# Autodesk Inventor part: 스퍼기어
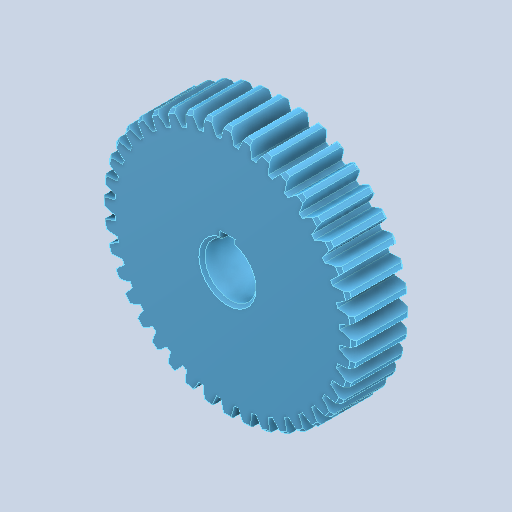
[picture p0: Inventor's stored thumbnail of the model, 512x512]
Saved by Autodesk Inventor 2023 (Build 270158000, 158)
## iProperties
Created: 2025-03
Part Number: 스퍼기어
Material: 알루미늄 6061
Document SubType Name: Modeling
Designer: ADMIN_PC
Density: 2.71 g/cm^3
Appearance: 기본값
Author: jhkim
Sending System: Autodesk Inventor 2025
Preprocessor: ST-DEVELOPER v20
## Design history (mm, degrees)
feature "Solid1"
node "솔리드1"
